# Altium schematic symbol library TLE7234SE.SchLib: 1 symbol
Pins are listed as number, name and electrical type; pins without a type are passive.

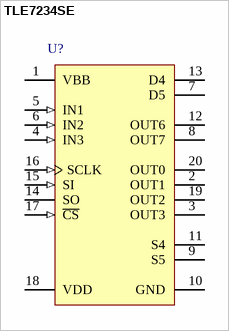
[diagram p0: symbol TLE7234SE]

## TLE7234SE
designator U?
SPI Driver for Enhanced Relay Control, 10 uA Quiescent Current, 3 to 5.5 V VDD, -40 to 150 degC, PG-DSO-20-45, Reel, Green; Manufacturer: Infineon; PartNumber: TLE7234SE; Channels: 8; Configurable channels: 2; Cranking mode: FALSE; Daisy-chain capability: TRUE; ID nom: 280 mA; ID(lim) (min): 0.5 A; Open Load Detection: off; Overcurrent limitation or shutdown: Shutdown; PWM Inputs: 3; Quiescent Current (max): 10 uA; RDS (on) (max): 1.8 Ohm; RDS (on) (typ): 0.85 Ohm; SPI: 8 Bit; VDD: 3 - 5.5 V; VDS(CL): 41 - 52 V
footprint INF-PG-DSO-20-45_N (SOP, 20-Leads, Body 12.7x7.5mm, Pitch 1.27mm, IPC Medium Density)
footprint INF-PG-DSO-20-45_L (SOP, 20-Leads, Body 12.7x7.5mm, Pitch 1.27mm, IPC High Density)
footprint INF-PG-DSO-20-45_M (SOP, 20-Leads, Body 12.7x7.5mm, Pitch 1.27mm, IPC Low Density)
pins: 1 VBB (power) "Power supply", 2 OUT1 (power) "Source of high side power transistor channel 1", 3 OUT3 (power) "Source of high side power transistor channel 3", 4 IN3 (in) "Input multiplexer input 3 pin (pull down)", 5 IN1 (in) "Input multiplexer input 1 pin (pull down)", 6 IN2 (in) "Input multiplexer input 2 pin (pull down)", 7 D5 (power) "Drain of auto configuring power transistor 5", 8 OUT7 (power) "Drain of low side power transistor channel 7", 9 S5 (power) "Source of auto configuring power transistor 5", 10 GND (power) "Digital,analog and power ground", 11 S4 (power) "Source of auto configuring power transistor 4", 12 OUT6 (power) "Drain of low side power transistor channel 6", 13 D4 (power) "Drain of auto configuring power transistor 4", 14 SO (hiz) "Serial data out", 15 SI (in) "Serial data in", 16 SCLK (in) "Serial clock", 17 ~{CS} (in) "SPI Chip select (pull up)", 18 VDD (power) "Digital power supply", 19 OUT2 (power) "Source of high side power transistor channel 2", 20 OUT0 (power) "Source of high side power transistor channel 0"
